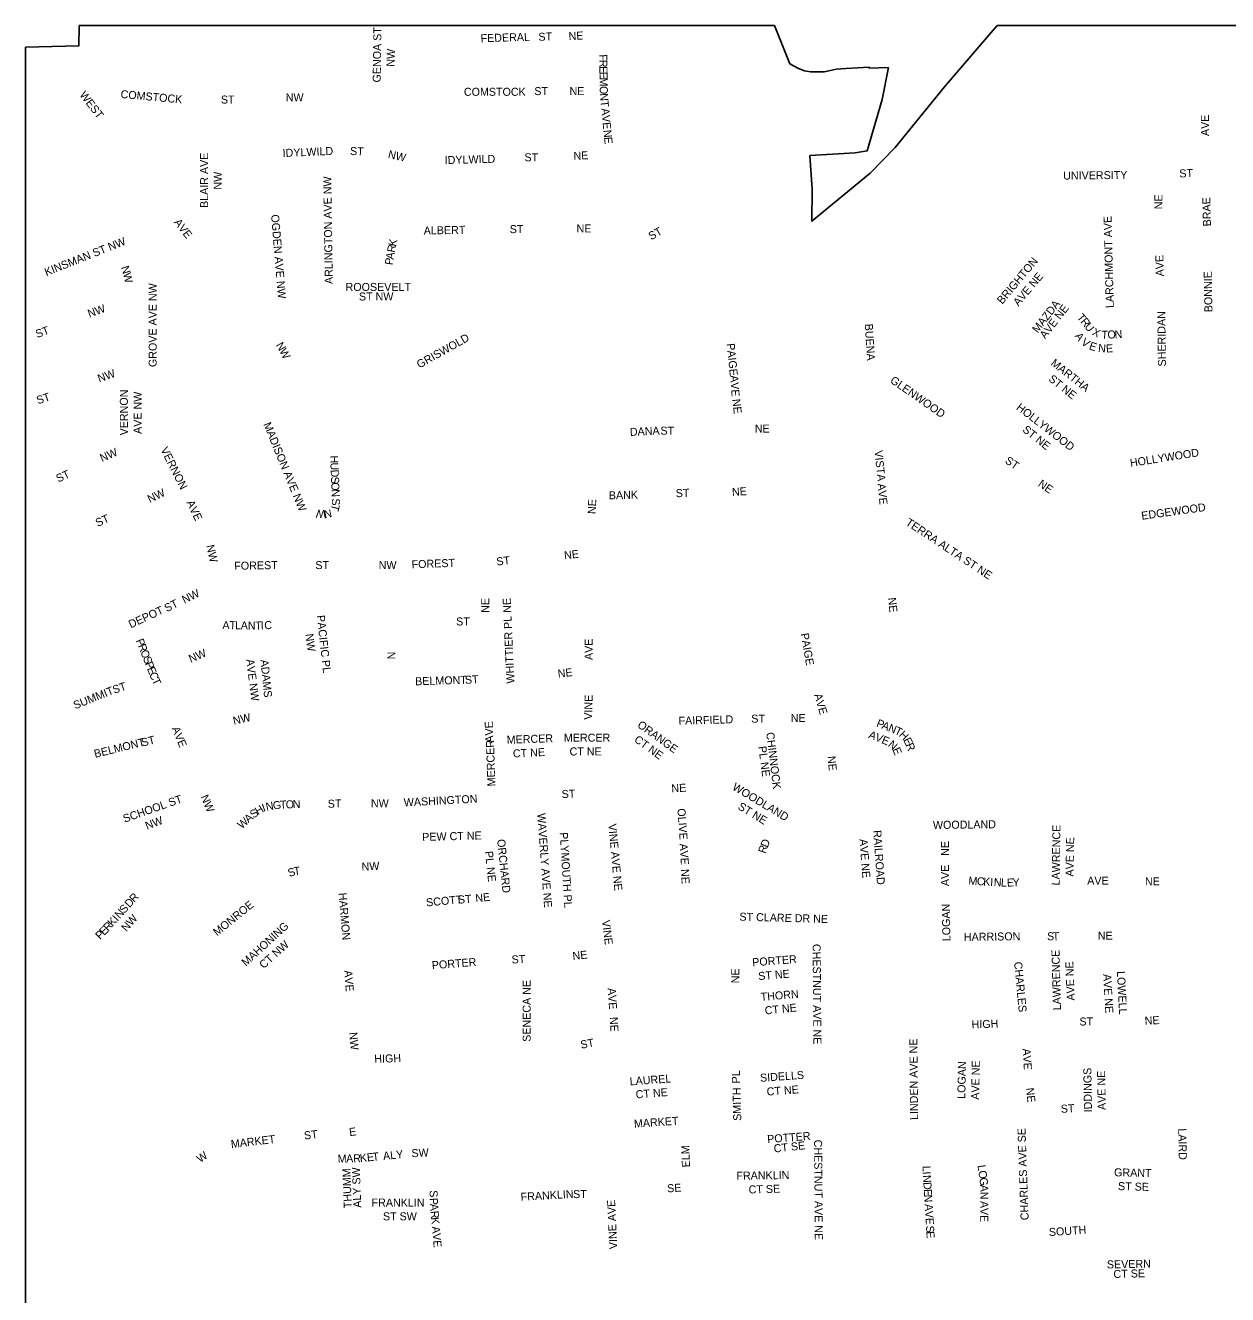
# Model space of a CAD drawing. Extents: x 0 to 34, y -0.1 to 32.4.
# Drawn here: x 2.94 to 4.363, y 30.857 to 32.359 of the extents above; entities that cross this region are included whole.
import ezdxf

# ---------------------------------------------------------------- set-up
doc = ezdxf.new("R2010")
doc.units = 0
doc.layers.add('GM_X_Interchange_Ramps', color=7, linetype='Continuous')
doc.layers.add('GM_X_US_Shield', color=7, linetype='Continuous')

msp = doc.modelspace()

# ---------------------------------------------------------------- linework, layer by layer
at = {"layer": 'GM_X_Interchange_Ramps'}
for p, q in [((3.8266, 32.3588), (3.0039, 32.3588)), ((4.7582, 32.3588), (4.09, 32.3588)), ((2.9404, 32.3331), (2.9404, 29.9441))]:
    msp.add_line(p, q, dxfattribs=at)
for points in [[(3.0039, 32.3588), (3.0036, 32.3346), (2.9404, 32.3331)], [(4.09, 32.3588), (4.0277, 32.286), (3.9695, 32.2142), (3.94, 32.1838), (3.871, 32.127), (3.8712, 32.1649), (3.8686, 32.2048), (3.9223, 32.2082), (3.9363, 32.2103), (3.9541, 32.2711), (3.9614, 32.3088), (3.9387, 32.308), (3.9387, 32.3092), (3.9112, 32.3077), (3.9001, 32.307), (3.8853, 32.3038), (3.8695, 32.3038), (3.8621, 32.3051), (3.855, 32.3077), (3.8448, 32.3134), (3.8266, 32.3588)]]:
    msp.add_lwpolyline(points, dxfattribs=at)

# ---------------------------------------------------------------- texts
at = {"layer": 'GM_X_US_Shield'}
for s, rotation, p in [('GENOA ST', 89.1579, (3.3607, 32.2912)), ('FEDERAL', 1.819, (3.4791, 32.3388)), ('ST', 2.2016, (3.5475, 32.3405)), ('NE', 3.0116, (3.5833, 32.3413)), ('NW', 87.5119, (3.3768, 32.3097)), ('F', 270.9835, (3.6193, 32.3245)), ('R', 270.9714, (3.6194, 32.3179)), ('E', 270.993, (3.6195, 32.3104)), ('E', 270.9835, (3.6197, 32.3037)), ('M', 270.9878, (3.6198, 32.297)), ('WEST', 307.4787, (3.0039, 32.2764)), ('COMSTOCK', 354.8042, (3.0527, 32.273)), ('ST', 0, (3.1717, 32.2663)), ('NW', 0, (3.2484, 32.2688)), ('COMSTOCK', 0, (3.4592, 32.2755)), ('ST', 0, (3.5425, 32.2763)), ('NE', 0, (3.5842, 32.2763)), ('O', 270.9618, (3.6199, 32.287)), ('N', 273.6031, (3.6201, 32.2782)), ('T', 275.7079, (3.6207, 32.2695)), ('A', 275.7887, (3.6216, 32.2604)), ('V', 275.8062, (3.6224, 32.2521)), ('E', 275.8019, (3.6233, 32.2438)), ('AVE', 90, (4.3407, 32.2279)), ('N', 275.8062, (3.6242, 32.2347)), ('IDYLWILD', 2.4898, (3.2449, 32.203)), ('ST', 357.7987, (3.3243, 32.2055)), ('E', 275.8019, (3.625, 32.2264)), ('BLAIR AVE', 90, (3.1566, 32.1428)), ('NW', 347.1975, (3.3688, 32.2021)), ('IDYLWILD', 1.6609, (3.4366, 32.1946)), ('ST', 0, (3.5309, 32.198)), ('NE', 3.0116, (3.5891, 32.1996)), ('NW', 90, (3.1727, 32.1645)), ('UNIVERSITY', 0.6899, (4.1683, 32.1763)), ('ST', 2.2016, (4.3058, 32.1788)), ('ARLINGTON AVE NW', 90.8196, (3.3041, 32.0528)), ('NE', 90, (4.2857, 32.1412)), ('BRAE', 91.5474, (4.3432, 32.1211)), ('AVE', 307.7447, (3.1156, 32.1256)), ('OGDEN AVE NW', 274.8073, (3.231, 32.1347)), ('ST', 0, (3.5134, 32.113)), ('NE', 0, (3.5925, 32.1138)), ('LARCHMONT AVE', 91.4313, (4.2282, 32.0245)), ('KINSMAN ST NW', 21.7046, (2.9652, 32.062)), ('ALBERT', 1.0603, (3.4117, 32.1113)), ('ST', 29.7491, (3.6808, 32.1044)), ('R', 77.89, (3.3773, 32.0894)), ('K', 77.732, (3.3788, 32.0967)), ('P', 81.7752, (3.3749, 32.0748)), ('A', 80.27, (3.3759, 32.0813)), ('BRIGHTON', 50.0937, (4.0962, 32.0282)), ('AVE', 91.468, (4.2874, 32.062)), ('N', 287.4466, (3.0534, 32.0726)), ('W', 283.0576, (3.0558, 32.0649)), ('AVE NE', 49.7658, (4.1153, 32.026)), ('BONNIE', 91.1053, (4.3449, 32.0195)), ('GROVE AVE NW', 90, (3.0957, 31.9545)), ('ROOSEVELT', 0, (3.3192, 32.0446)), ('ST NW', 0, (3.335, 32.0333)), ('MAZDA', 52.2218, (4.1381, 31.9941)), ('NW', 19.9823, (3.0161, 32.0129)), ('AVE NE', 52.2218, (4.147, 31.9872)), ('T', 309.398, (4.1839, 32.0131)), ('SHERIDAN', 90.818, (4.2899, 31.9553)), ('ST', 20.556, (2.9544, 31.9887)), ('BUENA', 273.5744, (3.9335, 32.0055)), ('R', 309.3842, (4.1882, 32.008)), ('U', 309.4081, (4.1929, 32.0022)), ('GRISWOLD', 29.3561, (3.4066, 31.9527)), ('A', 305.7943, (4.1815, 31.9912)), ('V', 324.4139, (4.1887, 31.982)), ('X', 333.3341, (4.2016, 31.993)), ('T', 358.8206, (4.2134, 31.9882)), ('O', 3.4502, (4.2209, 31.9881)), ('N', 3.4665, (4.2293, 31.9886)), ('N', 299.9591, (3.2364, 31.9806)), ('W', 298.024, (3.2405, 31.9735)), ('PAIGE', 275.7074, (3.7701, 31.9822)), ('E', 340.5427, (4.1981, 31.9759)), ('N', 354.9922, (4.2093, 31.9725)), ('E', 2.8977, (4.2191, 31.9717)), ('MARTHA', 321.789, (4.1528, 31.9576)), ('NW', 19.9823, (3.0278, 31.9362)), ('AVE', 273.9504, (3.7743, 31.9446)), ('GLENWOOD', 325.1257, (3.9627, 31.9368)), ('ST NE', 321.3424, (4.1501, 31.939)), ('VERNON', 90, (3.0616, 31.8737)), ('ST', 18.4363, (2.9553, 31.9104)), ('AVE NW', 90, (3.0779, 31.8754)), ('NE', 276.0054, (3.7768, 31.9164)), ('HOLLYWOOD', 322.2364, (4.1119, 31.9051)), ('MADISON AVE NW', 292.4061, (3.2217, 31.8869)), ('DANA', 2.8635, (3.6558, 31.873)), ('ST', 0, (3.6917, 31.8746)), ('NE', 0, (3.8034, 31.8771)), ('ST NE', 321.3389, (4.1193, 31.879)), ('NW', 23.1961, (3.031, 31.842)), ('VERNON', 296.5659, (3.1, 31.857)), ('VISTA', 275.5744, (3.9451, 31.8555)), ('HOLLYWOOD', 8.9398, (4.2481, 31.8363)), ('H', 272.3146, (3.3009, 31.8497)), ('U', 272.3146, (3.3012, 31.8414)), ('ST', 325.2957, (4.0985, 31.8418)), ('ST', 24.6211, (2.9793, 31.8178)), ('D', 272.3146, (3.3016, 31.833)), ('S', 272.3146, (3.3019, 31.8247)), ('NE', 325.4967, (4.1377, 31.8143)), ('NW', 25.4639, (3.0876, 31.7936)), ('O', 272.3146, (3.3022, 31.818)), ('N', 272.3146, (3.3025, 31.8097)), ('BANK', 1.4707, (3.6308, 31.798)), ('ST', 2.2058, (3.71, 31.8005)), ('NE', 3.011, (3.7766, 31.8021)), ('AVE', 275.9031, (3.9485, 31.8164)), ('AVE', 295.2809, (3.1308, 31.7944)), ('S', 272.3146, (3.3029, 31.7989)), ('NE', 86.8097, (3.6149, 31.7804)), ('EDGEWOOD', 7.9268, (4.2614, 31.7738)), ('ST', 24.6245, (3.0259, 31.7653)), ('W', 175.762, (3.2965, 31.785)), ('N', 191.8541, (3.3018, 31.7866)), ('T', 256.2225, (3.3033, 31.7929)), ('TERRA ALTA ST NE', 326.4346, (3.981, 31.7685)), ('NW', 282.8073, (3.1543, 31.7432)), ('NE', 6.0054, (3.5782, 31.7271)), ('FOREST', 1.1015, (3.1876, 31.7146)), ('ST', 0, (3.2834, 31.7155)), ('NW', 0, (3.3584, 31.7155)), ('FOREST', 2.2036, (3.3975, 31.7163)), ('ST', 6.5823, (3.4982, 31.7196)), ('NW', 25.4639, (3.1284, 31.6745)), ('DEPOT', 24.8625, (3.0651, 31.6453)), ('ST', 26.565, (3.1076, 31.6644)), ('NE', 90, (3.4891, 31.6637)), ('WHITTIER PL NE', 92.627, (3.5191, 31.5803)), ('NE', 276.0054, (3.961, 31.6814)), ('PACIFIC PL', 276.3399, (3.2851, 31.6605)), ('ST', 0, (3.45, 31.6488)), ('A', 358.776, (3.1734, 31.6446)), ('T', 358.7957, (3.1817, 31.6445)), ('L', 358.7843, (3.1884, 31.6443)), ('A', 358.776, (3.1951, 31.6442)), ('N', 359.3453, (3.2035, 31.644)), ('T', 1.689, (3.2123, 31.6439)), ('I', 2.2402, (3.219, 31.6441)), ('C', 2.2854, (3.2232, 31.6443)), ('P', 291.7152, (3.0708, 31.631)), ('R', 291.7121, (3.0733, 31.6248)), ('NW', 277.4371, (3.2716, 31.6385)), ('AVE', 90, (3.6116, 31.6079)), ('PAIGE', 279.926, (3.8576, 31.639)), ('O', 291.7152, (3.0761, 31.6178)), ('S', 291.7202, (3.0792, 31.6101)), ('NW', 23.1961, (3.136, 31.6045)), ('N', 90, (3.3782, 31.6087)), ('P', 291.7202, (3.0816, 31.6039)), ('E', 291.7152, (3.0841, 31.5977)), ('AVE NW', 277.2531, (3.2015, 31.6085)), ('ADAMS', 275.7119, (3.2185, 31.608)), ('NE', 6.0123, (3.5707, 31.5871)), ('ST', 18.4328, (3.0453, 31.5679)), ('C', 291.7121, (3.0866, 31.5915)), ('T', 294.8117, (3.0896, 31.584)), ('BELMONT', 1.7105, (3.4016, 31.578)), ('ST', 3.5746, (3.4607, 31.5796)), ('SUMMIT', 21.9918, (2.9994, 31.5495)), ('AVE', 286.5536, (3.8734, 31.5667)), ('VINE', 88.2652, (3.6107, 31.5371)), ('NW', 12.8073, (3.1871, 31.5313)), ('FAIRFIELD', 1.6125, (3.7133, 31.5313)), ('ST', 0, (3.7992, 31.5338)), ('NE', 0, (3.8459, 31.5346)), ('P', 338.4878, (3.9465, 31.5295)), ('AVE', 292.6194, (3.1133, 31.5269)), ('AVE', 91.9814, (3.4941, 31.5103)), ('ORANGE', 324.1181, (3.6636, 31.5293)), ('CHINNOCK', 277.0275, (3.8168, 31.5219)), ('A', 338.2006, (3.9371, 31.516)), ('V', 338.1032, (3.9449, 31.513)), ('A', 338.4953, (3.9527, 31.5271)), ('N', 338.4847, (3.9604, 31.524)), ('T', 334.2659, (3.968, 31.521)), ('H', 315.5641, (3.9733, 31.5186)), ('BELMONT', 13.828, (3.0229, 31.4921)), ('ST', 14.0362, (3.0788, 31.5054)), ('MERCER', 92.0085, (3.4966, 31.4586)), ('MERCER', 2.0104, (3.51, 31.5088)), ('MERCER', 0, (3.5775, 31.5113)), ('CT NE', 323.9732, (3.6598, 31.512)), ('E', 337.397, (3.9526, 31.5099)), ('N', 318.921, (3.9603, 31.5067)), ('E', 295.508, (3.9788, 31.5135)), ('R', 291.6661, (3.9816, 31.5076)), ('CT NE', 2.8635, (3.5174, 31.4925)), ('CT NE', 0, (3.5842, 31.495)), ('PL NE', 277.4974, (3.8075, 31.5055)), ('NE', 276.0168, (3.8893, 31.4939)), ('E', 293.43, (3.9659, 31.5021)), ('NE', 3.0116, (3.7049, 31.4513)), ('WOODLAND', 329.0362, (3.7759, 31.4552)), ('SCHOOL ST', 19.3978, (3.0578, 31.4154)), ('NW', 293.1961, (3.1475, 31.4461)), ('WASHINGTON', 3.0442, (3.3883, 31.4346)), ('ST', 2.2055, (3.575, 31.4446)), ('S', 38.3782, (3.2105, 31.4201)), ('H', 31.4192, (3.2155, 31.4241)), ('I', 19.6862, (3.2222, 31.4282)), ('N', 10.4827, (3.2257, 31.4295)), ('G', 6.9135, (3.2337, 31.431)), ('T', 2.9388, (3.2418, 31.432)), ('O', 1.8473, (3.2485, 31.4323)), ('N', 1.7926, (3.2568, 31.4326)), ('ST', 2.2013, (3.2983, 31.433)), ('NW', 0, (3.3492, 31.4338)), ('OLIVE', 274.0834, (3.7118, 31.4321)), ('ST NE', 328.7817, (3.7825, 31.4321)), ('NW', 20.8577, (3.0843, 31.407)), ('W', 41.5798, (3.1963, 31.4075)), ('A', 41.5835, (3.2044, 31.4147)), ('WAVERLY AVE NE', 274.1844, (3.546, 31.4263)), ('WOODLAND', 0.6983, (4.0142, 31.408)), ('PEW CT NE', 1.5685, (3.41, 31.3938)), ('PLYMOUTH PL', 273.5376, (3.5726, 31.4038)), ('VINE AVE NE', 275.2559, (3.6301, 31.4138)), ('RAILROAD', 273.9703, (3.9435, 31.4063)), ('LAWRENCE', 89.2535, (4.1641, 31.3412)), ('ORCHARD', 275.8773, (3.4985, 31.3955)), ('AVE', 273.9431, (3.7143, 31.3905)), ('R', 70.6165, (3.8159, 31.3783)), ('D', 67.2204, (3.8184, 31.3853)), ('AVE NE', 274.4823, (3.9272, 31.3959)), ('NE', 90, (4.0332, 31.3762)), ('AVE NE', 88.873, (4.1804, 31.3517)), ('PL NE', 276.0114, (3.4841, 31.3814)), ('S', 19.7917, (3.2528, 31.351)), ('T', 8.1552, (3.2586, 31.3532)), ('NW', 2.4879, (3.3383, 31.3588)), ('NE', 273.011, (3.716, 31.3604)), ('AVE', 90, (4.0332, 31.3404)), ('M', 356.7929, (4.056, 31.3421)), ('C', 356.802, (4.0659, 31.3416)), ('K', 356.7959, (4.0734, 31.3412)), ('I', 356.7862, (4.0817, 31.3407)), ('N', 356.7895, (4.0859, 31.3405)), ('L', 358.4557, (4.0945, 31.34)), ('E', 1.9022, (4.1018, 31.3398)), ('Y', 2.6083, (4.1086, 31.34)), ('AVE', 0, (4.1967, 31.3421)), ('NE', 0, (4.265, 31.3413)), ('R', 47.9521, (3.0693, 31.3204)), ('HARMON', 274.6116, (3.311, 31.3322)), ('SCOTT', 5.1942, (3.4149, 31.3163)), ('ST', 4.4003, (3.4524, 31.3196)), ('NE', 6.0066, (3.4732, 31.3213)), ('N', 47.9454, (3.052, 31.3013)), ('S', 47.9551, (3.0575, 31.3074)), ('D', 47.9454, (3.0637, 31.3143)), ('MONROE', 38.9555, (3.1672, 31.2809)), ('LOGAN', 91.1685, (4.0349, 31.2753)), ('R', 47.3139, (3.0384, 31.2864)), ('K', 47.9174, (3.0436, 31.292)), ('I', 47.9654, (3.0492, 31.2982)), ('NW', 48.5706, (3.0599, 31.2859)), ('MAHONING', 42.374, (3.2013, 31.245)), ('VINE', 276.9138, (3.6226, 31.2997)), ('ST CLARE DR NE', 358.4376, (3.7851, 31.2996)), ('P', 45.0773, (3.0288, 31.2766)), ('E', 45.4551, (3.0335, 31.2814)), ('HARRISON', 0.8065, (4.0508, 31.2755)), ('S', 0.5055, (4.1492, 31.2763)), ('T', 0.5101, (4.1559, 31.2764)), ('NE', 0, (4.2092, 31.2771)), ('CT NW', 42.1858, (3.2223, 31.2421)), ('CHESTNUT AVE NE', 270.4513, (3.8718, 31.272)), ('PORTER', 4.3159, (3.4216, 31.2421)), ('ST', 2.2013, (3.5158, 31.2488)), ('NE', 6.0123, (3.5882, 31.253)), ('PORTER', 4.3177, (3.8007, 31.2455)), ('LAWRENCE', 91.4899, (4.1657, 31.1936)), ('AVE NE', 92.2488, (4.182, 31.2051)), ('AVE', 274.4019, (3.3176, 31.2405)), ('NE', 90, (3.7849, 31.2254)), ('ST NE', 4.5141, (3.8078, 31.2292)), ('CHARLES', 275.4408, (4.1101, 31.2505)), ('AVE NE', 273.3689, (4.2155, 31.2362)), ('LOWELL', 273.015, (4.2318, 31.2396)), ('SENECA NE', 90, (3.5382, 31.1562)), ('AVE', 273.9506, (3.6293, 31.2196)), ('THORN', 4.7633, (3.8107, 31.2046)), ('CT NE', 5.7106, (3.8156, 31.1884)), ('NE', 273.0113, (3.6318, 31.1854)), ('HIGH', 1.6357, (4.06, 31.1721)), ('ST', 0, (4.1875, 31.1755)), ('NE', 3.0116, (4.2649, 31.1763)), ('NW', 274.9669, (3.3235, 31.1672)), ('ST', 10.6188, (3.598, 31.1479)), ('LINDEN AVE NE', 90.5402, (3.9966, 31.0637)), ('AVE', 273.9431, (4.1201, 31.148)), ('HIGH', 1.6357, (3.3533, 31.1313)), ('LOGAN', 88.8315, (4.0524, 31.0887)), ('AVE NE', 88.8773, (4.0687, 31.0876)), ('LAUREL', 4.1593, (3.6557, 31.1046)), ('PL', 90, (3.7857, 31.107)), ('SIDELLS', 4.0853, (3.8099, 31.1088)), ('IDDINGS', 91.0045, (4.2024, 31.0728)), ('AVE NE', 91.1227, (4.2187, 31.0756)), ('CT NE', 4.2894, (3.6628, 31.0892)), ('SMITH', 91.3315, (3.7874, 31.0628)), ('CT NE', 4.2894, (3.8178, 31.0925)), ('NE', 276.006, (4.1243, 31.1014)), ('ST', 3.5738, (4.1657, 31.0721)), ('MARKET', 3.88, (3.6607, 31.0546)), ('MARKET', 6.613, (3.184, 31.0305)), ('ST', 7.1217, (3.2706, 31.0405)), ('E', 7.1217, (3.324, 31.0446)), ('POTTER', 4.3982, (3.8184, 31.0363)), ('CHARLES AVE SE', 91.9929, (4.1274, 30.9453)), ('LAIRD', 271.3632, (4.3043, 31.0537)), ('W', 36.0309, (3.1473, 31.0126)), ('ALY', 5.8559, (3.364, 31.0163)), ('SW', 2.8668, (3.3974, 31.0196)), ('ELM', 91.9739, (3.7267, 31.0078)), ('CT SE', 6.1693, (3.8263, 31.0251)), ('CHESTNUT AVE NE', 270.4506, (3.8735, 31.0404)), ('M', 1.7854, (3.31, 31.013)), ('A', 1.7846, (3.32, 31.0133)), ('R', 2.149, (3.3284, 31.0135)), ('K', 5.0179, (3.3364, 31.0139)), ('E', 6.0833, (3.3449, 31.0146)), ('T', 6.1211, (3.3515, 31.0153)), ('THUMM', 92.1599, (3.3266, 30.9595)), ('ALY SW', 92.1599, (3.3379, 30.96)), ('FRANKLIN', 0.818, (3.7817, 30.993)), ('L', 271.9947, (4.0018, 31.0094)), ('I', 273.266, (4.002, 31.0025)), ('N', 273.439, (4.0023, 30.9983)), ('L', 278.9705, (4.0668, 31.0098)), ('O', 278.9835, (4.0678, 31.0032)), ('GRANT', 358.8049, (4.2284, 30.9971)), ('FRANKLIN', 3.2703, (3.5266, 30.968)), ('ST', 0, (3.5884, 30.9713)), ('SE', 3.5746, (3.6999, 30.978)), ('CT SE', 1.5472, (3.7962, 30.9767)), ('D', 273.4787, (4.0028, 30.99)), ('E', 273.4715, (4.0033, 30.9817)), ('G', 276.3957, (4.0691, 30.9951)), ('A', 270.8088, (4.07, 30.9871)), ('ST SE', 358.4067, (4.233, 30.9808)), ('FRANKLIN', 0, (3.35, 30.9613)), ('S', 272.3228, (3.4185, 30.9804)), ('P', 272.3218, (3.4188, 30.9713)), ('VINE AVE', 92.6411, (3.6407, 30.9111)), ('N', 273.4557, (4.0037, 30.9751)), ('N', 270, (4.0701, 30.9788)), ('A', 270, (4.0701, 30.9679)), ('ST SW', 0, (3.3634, 30.945)), ('A', 273.546, (3.4191, 30.9644)), ('R', 275.1314, (3.4197, 30.9558)), ('A', 273.4775, (4.0044, 30.9642)), ('V', 273.4557, (4.0049, 30.9559)), ('V', 269.9928, (4.0701, 30.9596)), ('K', 275.1995, (3.4203, 30.9483)), ('A', 275.1869, (3.4213, 30.9375)), ('E', 273.48, (4.0054, 30.9476)), ('S', 273.4715, (4.0059, 30.9384)), ('E', 269.9956, (4.0701, 30.9513)), ('SOUTH', 3.7316, (4.1516, 30.9263)), ('V', 275.1995, (3.4221, 30.9292)), ('E', 275.1982, (3.4228, 30.9209)), ('E', 273.4736, (4.0063, 30.9318)), ('SEVERN', 1.0603, (4.22, 30.888)), ('CT SE', 1.5474, (4.2278, 30.8767))]:
    msp.add_text(s, height=0.00947, rotation=rotation, dxfattribs=at).set_placement(p)

doc.saveas('drawing.dxf')
